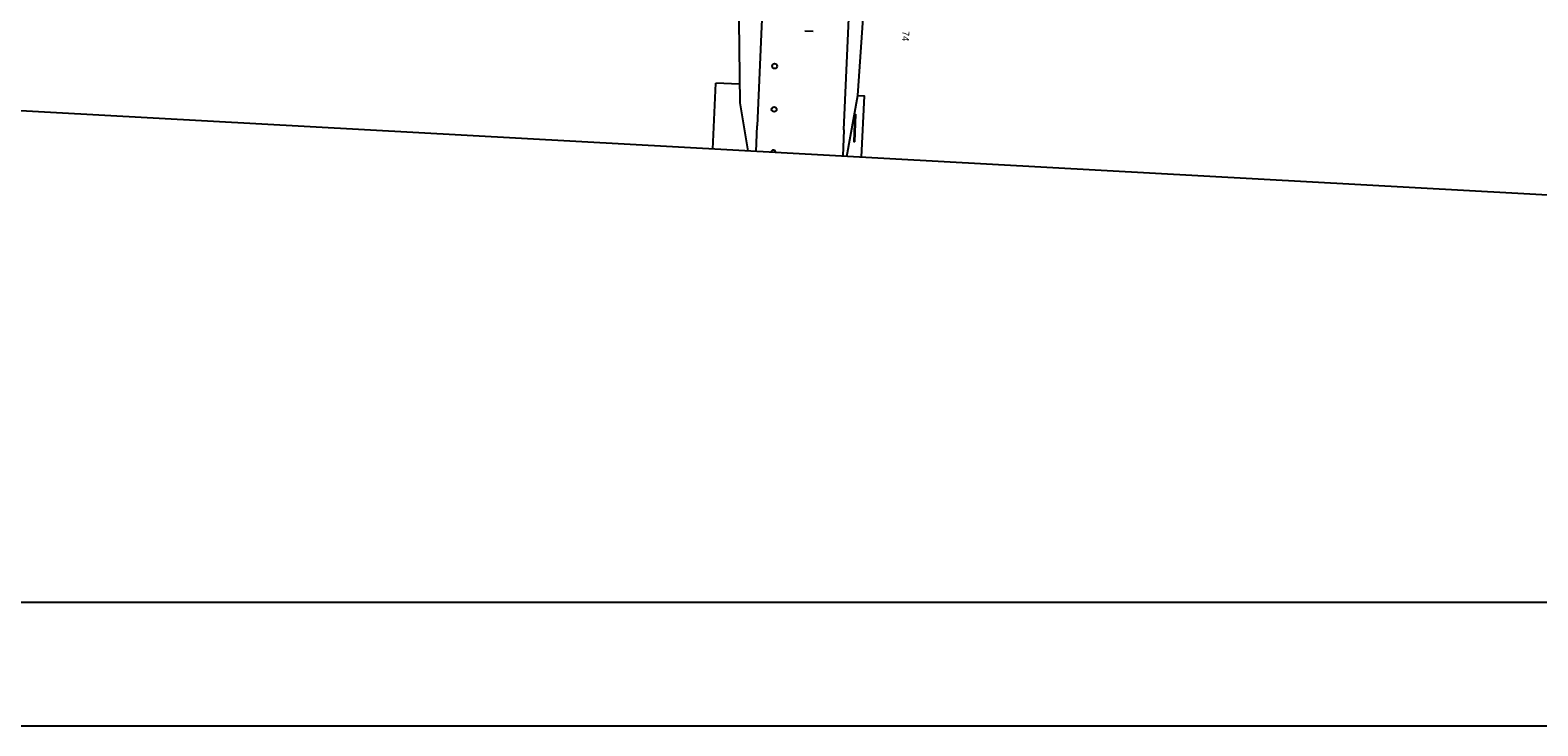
# Model space of a CAD drawing. Extents: x 0 to 1361828, y 0 to 1470398.
# Drawn here: x 685616 to 686834, y 733868 to 734431 of the extents above; entities that cross this region are included whole.
import ezdxf

# ---------------------------------------------------------------- set-up
doc = ezdxf.new("R2010")
doc.units = 0
for name, color, linetype in [('$', 7, 'Continuous'), ('border All Plan 20-40 - Level 1', 7, 'Continuous'), ('C-TOPO', 7, 'Continuous'), ('C-TOPO-FEAT', 7, 'Continuous'), ('MOT Stage 1', 7, 'Continuous'), ('R_Horz Alg Station', 7, 'Continuous'), ('R_TYPE_A_CURB', 7, 'Continuous'), ('RW-EX', 7, 'Continuous'), ('RW-PR', 7, 'Continuous'), ('V-NODE', 7, 'Continuous')]:
    doc.layers.add(name, color=color, linetype=linetype)

# ---------------------------------------------------------------- blocks, each defined once
blk = doc.blocks.new('BAREL_1872')
at = {"layer": 'MOT Stage 1'}
blk.add_circle((0, 0), 2.88, dxfattribs=at)
blk = doc.blocks.new('BAREL_1873')
at = {"layer": 'MOT Stage 1'}
blk.add_circle((0, 0), 2.88, dxfattribs=at)

msp = doc.modelspace()

# ---------------------------------------------------------------- linework, layer by layer
at = {"layer": '$'}
msp.add_lwpolyline([(679553.9, 733968.3), (687571.1, 733968.3), (687571.1, 736006.7), (679553.9, 736006.7), (679553.9, 733968.3)], dxfattribs=at)
at = {"layer": 'border All Plan 20-40 - Level 1'}
msp.add_line((686968.5, 734290.2), (685390, 734377.6), dxfattribs=at)
at = {"layer": 'C-TOPO'}
msp.add_lwpolyline([(679453.9, 733868.3), (687671.1, 733868.3), (687671.1, 736106.7), (679453.9, 736106.7), (679453.9, 733868.3)], dxfattribs=at)
at = {"layer": 'C-TOPO-FEAT'}
msp.add_lwpolyline([(679553.9, 733968.3), (687571.1, 733968.3), (687571.1, 736006.7), (679553.9, 736006.7), (679553.9, 733968.3)], dxfattribs=at)
at = {"layer": 'MOT Stage 1'}
msp.add_arc((686216.7, 734331.6), 2, 4.1955, 169.4622, dxfattribs=at)
at = {"layer": 'R_Horz Alg Station'}
msp.add_lwpolyline([(686248.8, 734429.5), (686242.1, 734429.8)], dxfattribs=at)
at = {"layer": 'R_TYPE_A_CURB'}
for p, q in [((686282.5, 734362.8), (686281.6, 734340.3)), ((686283, 734362.8), (686282.1, 734340.3)), ((686282.5, 734362.8), (686283, 734362.8)), ((686281.6, 734340.3), (686282.1, 734340.3))]:
    msp.add_line(p, q, dxfattribs=at)
at = {"layer": 'RW-EX'}
for p, q in [((686273.7, 734350.1), (686287, 734655.9)), ((686208.3, 734458.9), (686203.7, 734353.2)), ((686273.7, 734350.1), (686272.7, 734328.7))]:
    msp.add_line(p, q, dxfattribs=at)
msp.add_lwpolyline([(686202.8, 734332.6), (686203.7, 734353.2)], dxfattribs=at)
at = {"layer": 'RW-PR'}
for p in [(686167.9, 734334.5), (686189.3, 734387)]:
    msp.add_line(p, (686170.2, 734387.9), dxfattribs=at)
for points in [[(685416.5, 734855.9), (685615.3, 734844.5), (685918.8, 734822.8), (685992.9, 734807.5), (686092.7, 734800.3), (686145.5, 734791.5), (686191.4, 734759.5), (686200.2, 734731.9), (686188.4, 734460.2), (686189.5, 734372), (686196, 734333)], [(686275.9, 734328.5), (686284.9, 734377.9), (686298.6, 734577.5), (686317.9, 734676.7), (686320.1, 734726.7), (686331.2, 734751.2)], [(686284.9, 734377.9), (686289.9, 734377.6), (686287.7, 734327.9)]]:
    msp.add_lwpolyline(points, dxfattribs=at)
at = {"layer": 'V-NODE'}
msp.add_lwpolyline([(679553.9, 733968.3), (687571.1, 733968.3), (687571.1, 736006.7), (679553.9, 736006.7), (679553.9, 733968.3)], dxfattribs=at)

# ---------------------------------------------------------------- block references
at = {"layer": 'MOT Stage 1', "xscale": 0.6945420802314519, "yscale": 0.6945420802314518, "rotation": 87.04179557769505}
for name, p in [('BAREL_1873', (686217.7, 734401.6)), ('BAREL_1872', (686217.3, 734366.6))]:
    msp.add_blockref(name, p, dxfattribs=at)

# ---------------------------------------------------------------- texts
at = {"layer": '$'}
msp.add_text('74', height=5.6, rotation=267.5058, dxfattribs=at).set_placement((686320.9, 734430.1))

doc.saveas('drawing.dxf')
